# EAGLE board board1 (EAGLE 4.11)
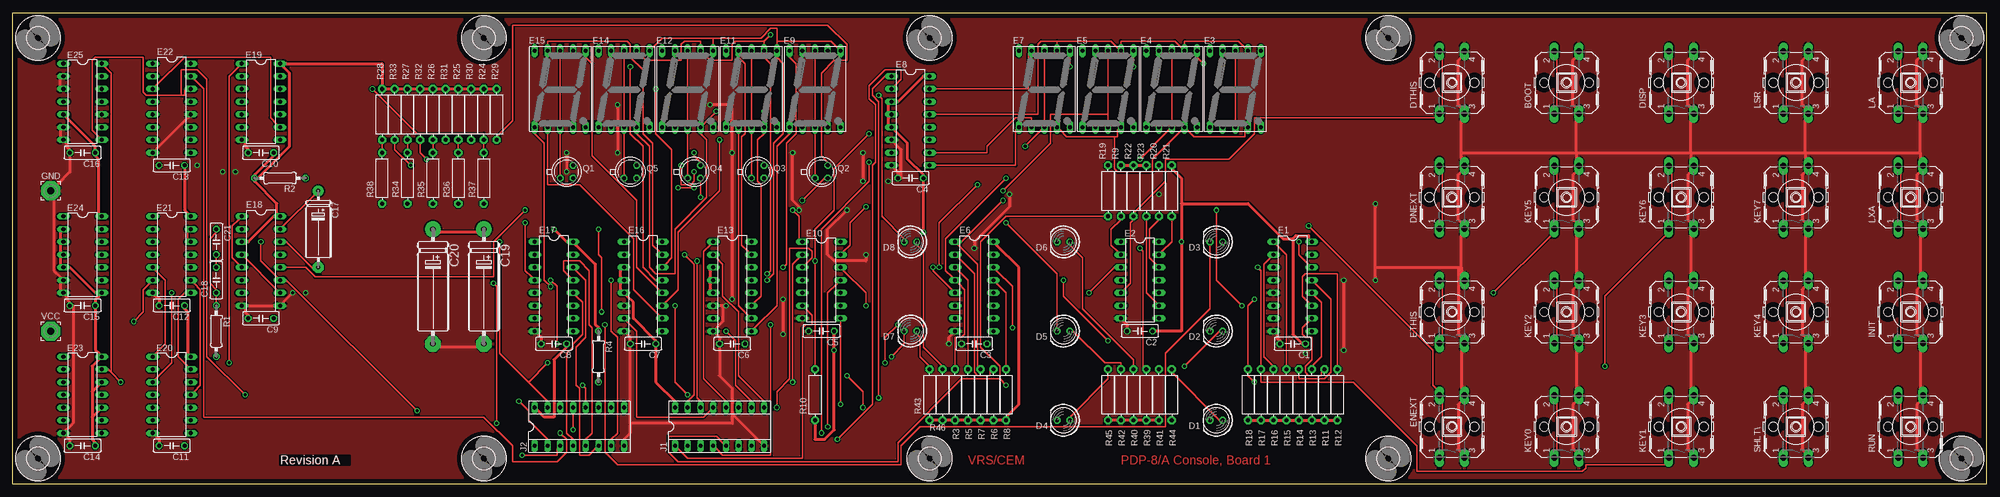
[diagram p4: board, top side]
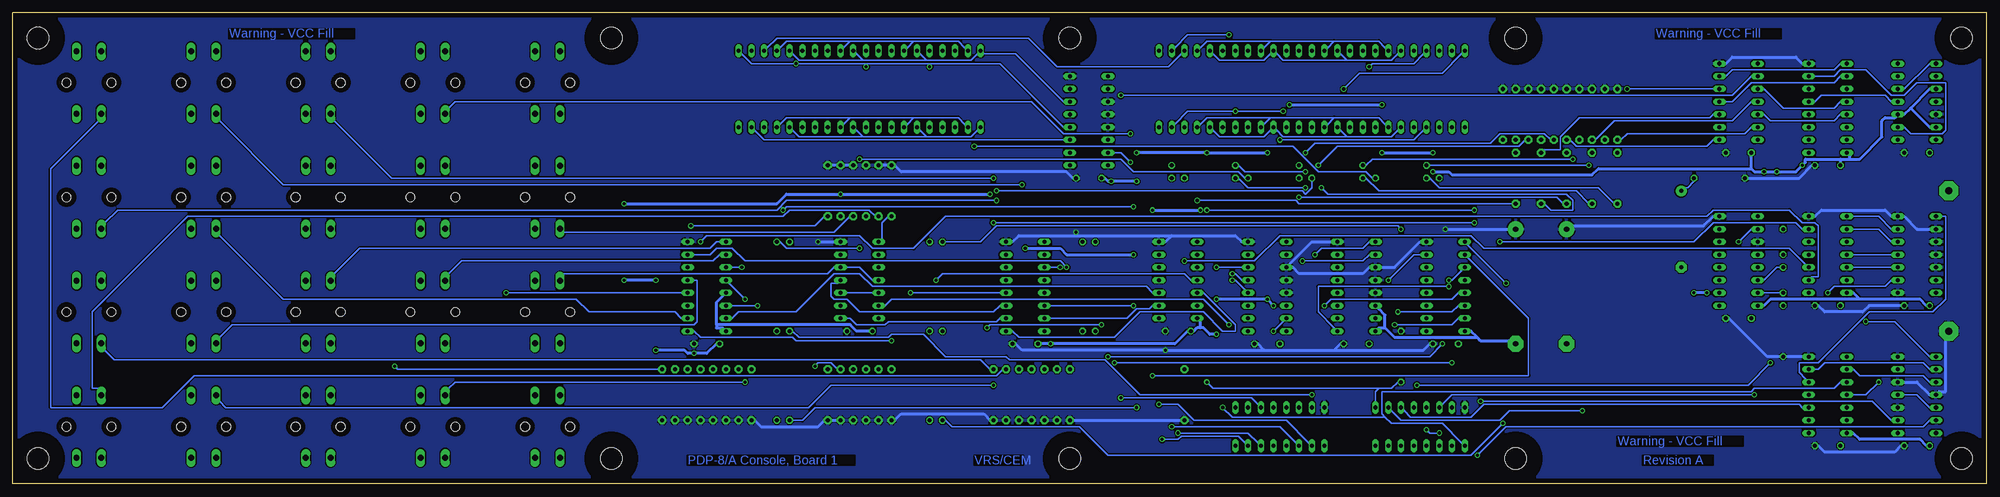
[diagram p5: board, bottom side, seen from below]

Size 393.7 x 93.98 mm. Coordinates in mm from the lower left corner, seen from the top.
Outline: 0,0 0,93.98 393.7,93.98 393.7,0 0,0
Copper layers (1*16): Top 0.035mm / dielectric 1.5mm / Bottom 0.035mm
Design rules "olimex10mil": minimum track width 10mil, minimum drill 24mil, track to track 10mil, track to pad 10mil, pad to pad 10mil, via to via 10mil, smd to smd 10mil, copper to edge 40mil, drill to drill 10mil, minimum pad ring 10mil, minimum via ring 8mil, stop-mask expansion 0mil, vias tented up to drill 0mil, thermal gap 10mil
Net classes: 1 Supply: width 0.635 mm

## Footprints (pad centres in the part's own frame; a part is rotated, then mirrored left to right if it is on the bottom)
B3F-40XX = drill 1.194 long: 1 -6.248,2.489; 2 6.248,2.489; 3 -6.248,-2.489; 4 6.248,-2.489 | hole 1.803: 0,-4.496; 0,4.496
C050-025X075 = drill 0.813 octagon: 1 -2.54,0; 2 2.54,0
E15-5 = drill 0.813 pad 2.159 round: + -7.62,0 | drill 0.813 pad 2.159 octagon: - 7.62,0
E22-6 = drill 1.016 pad 3.15 round: + -11.43,0 | drill 1.016 pad 3.15 octagon: - 11.43,0
LED5MM = drill 0.813 octagon: A -1.27,0; K 1.27,0
DIL16 = drill 0.813 long: 1 -8.89,-3.81; 2 -6.35,-3.81; 3 -3.81,-3.81; 4 -1.27,-3.81; 5 1.27,-3.81; 6 3.81,-3.81; 7 6.35,-3.81; 8 8.89,-3.81; 9 8.89,3.81; 10 6.35,3.81; 11 3.81,3.81; 12 1.27,3.81; 13 -1.27,3.81; 14 -3.81,3.81; 15 -6.35,3.81; 16 -8.89,3.81
DIL14 = drill 0.813 long: 1 -7.62,-3.81; 2 -5.08,-3.81; 3 -2.54,-3.81; 4 0,-3.81; 5 2.54,-3.81; 6 5.08,-3.81; 7 7.62,-3.81; 8 7.62,3.81; 9 5.08,3.81; 10 2.54,3.81; 11 0,3.81; 12 -2.54,3.81; 13 -5.08,3.81; 14 -7.62,3.81
HDSP-M = drill 0.813 long: 1 -5.08,-7.62; 2 -2.54,-7.62; 3 0,-7.62; 4 2.54,-7.62; 5 5.08,-7.62; 6 5.08,7.62; 7 2.54,7.62; 8 0,7.62; 9 -2.54,7.62; 10 -5.08,7.62
3,81/1,4 = drill 1.397 pad 3.81 octagon: 1 0,0
SOCKED-16 = drill 0.813 long: 1 -8.89,-3.81; 2 -6.35,-3.81; 3 -3.81,-3.81; 4 -1.27,-3.81; 5 1.27,-3.81; 6 3.81,-3.81; 7 6.35,-3.81; 8 8.89,-3.81; 9 8.89,3.81; 10 6.35,3.81; 11 3.81,3.81; 12 1.27,3.81; 13 -1.27,3.81; 14 -3.81,3.81; 15 -6.35,3.81; 16 -8.89,3.81
TO18 = drill 0.813 octagon: 1 -1.27,-1.27; 2 1.27,-1.27; 3 1.27,1.27
0207/10 = drill 0.813 octagon: 1 -5.08,0; 2 5.08,0
R-10 = drill 0.813 pad 1.6 octagon: 1 -5.08,0; 2 5.08,0
4,3 = hole 4.3: 0,0

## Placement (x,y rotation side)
BOOT  [B3F-40XX]  309.88,80.01 90 top
C1  0.01  [C050-025X075]  255.27,27.94 180 top
C2  0.01  [C050-025X075]  224.79,30.48 180 top
C3  0.01  [C050-025X075]  191.77,27.94 180 top
C4  0.01  [C050-025X075]  179.07,60.96 180 top
C5  0.01  [C050-025X075]  161.29,30.48 180 top
C6  0.01  [C050-025X075]  143.51,27.94 180 top
C7  0.01  [C050-025X075]  125.73,27.94 180 top
C8  0.01  [C050-025X075]  107.95,27.94 180 top
C9  0.01  [C050-025X075]  49.53,33.02 180 top
C10  0.01  [C050-025X075]  49.53,66.04 180 top
C11  0.01  [C050-025X075]  31.75,7.62 180 top
C12  0.01  [C050-025X075]  31.75,35.56 180 top
C13  0.01  [C050-025X075]  31.75,63.5 180 top
C14  0.01  [C050-025X075]  13.97,7.62 180 top
C15  0.01  [C050-025X075]  13.97,35.56 180 top
C16  0.01  [C050-025X075]  13.97,66.04 180 top
C17  1.0uf  [E15-5]  60.96,50.8 270 top
C18  47pf  [C050-025X075]  40.64,40.64 90 top
C19  220uf  [E22-6]  93.98,39.37 270 top
C20  6.8uf  [E22-6]  83.82,39.37 270 top
C21  33pf  [C050-025X075]  40.64,48.26 270 top
D1  MQ  [LED5MM]  240.03,12.7 180 top
D2  SR  [LED5MM]  240.03,30.48 180 top
D3  MD  [LED5MM]  240.03,48.26 180 top
D4  AC  [LED5MM]  209.55,12.7 180 top
D5  STATUS  [LED5MM]  209.55,30.48 180 top
D6  STATE  [LED5MM]  209.55,48.26 180 top
D7  BUS  [LED5MM]  179.07,30.48 180 top
D8  RUN  [LED5MM]  179.07,48.26 180 top
DISP  [B3F-40XX]  332.74,80.01 90 top
DNEXT  [B3F-40XX]  287.02,57.15 90 top
DTHIS  [B3F-40XX]  287.02,80.01 90 top
E1  74LS148N  [DIL16]  255.27,39.37 270 top
E2  74LS08N  [DIL14]  224.79,40.64 270 top
E3  HD-H101  [HDSP-M]  243.84,78.74 0 top
E4  HD-H101  [HDSP-M]  231.14,78.74 0 top
E5  HD-H101  [HDSP-M]  218.44,78.74 0 top
E6  74LS148N  [DIL16]  191.77,39.37 270 top
E7  HD-H101  [HDSP-M]  205.74,78.74 0 top
E8  7446N  [DIL16]  179.07,72.39 270 top
E9  HD-H101  [HDSP-M]  160.02,78.74 0 top
E10  74LS08N  [DIL14]  161.29,40.64 270 top
E11  HD-H101  [HDSP-M]  147.32,78.74 0 top
E12  HD-H101  [HDSP-M]  134.62,78.74 0 top
E13  7446N  [DIL16]  143.51,39.37 270 top
E14  HD-H101  [HDSP-M]  121.92,78.74 0 top
E15  HD-H101  [HDSP-M]  109.22,78.74 0 top
E16  7446N  [DIL16]  125.73,39.37 270 top
E17  74LS145N  [DIL16]  107.95,39.37 270 top
E18  74LS123N  [DIL16]  49.53,44.45 270 top
E19  7416N  [DIL14]  49.53,76.2 270 top
E20  74LS04N  [DIL14]  31.75,17.78 270 top
E21  74LS20N  [DIL14]  31.75,45.72 270 top
E22  74LS42N  [DIL16]  31.75,74.93 270 top
E23  74LS74N  [DIL14]  13.97,17.78 270 top
E24  74LS95N  [DIL14]  13.97,45.72 270 top
E25  74LS90N  [DIL14]  13.97,76.2 270 top
ENEXT  [B3F-40XX]  287.02,11.43 90 top
ETHIS  [B3F-40XX]  287.02,34.29 90 top
GND  [3,81/1,4]  7.62,58.42 0 top
INIT  [B3F-40XX]  378.46,34.29 90 top
J1  [SOCKED-16]  140.97,11.43 0 top
J2  [SOCKED-16]  113.03,11.43 0 top
KEY0  [B3F-40XX]  309.88,11.43 90 top
KEY1  [B3F-40XX]  332.74,11.43 90 top
KEY2  [B3F-40XX]  309.88,34.29 90 top
KEY3  [B3F-40XX]  332.74,34.29 90 top
KEY4  [B3F-40XX]  355.6,34.29 90 top
KEY5  [B3F-40XX]  309.88,57.15 90 top
KEY6  [B3F-40XX]  332.74,57.15 90 top
KEY7  [B3F-40XX]  355.6,57.15 90 top
LA  [B3F-40XX]  378.46,80.01 90 top
LSR  [B3F-40XX]  355.6,80.01 90 top
LXA  [B3F-40XX]  378.46,57.15 90 top
Q1  MPSA05  [TO18]  110.49,62.23 0 top
Q2  MPSA05  [TO18]  161.29,62.23 0 top
Q3  MPSA05  [TO18]  148.59,62.23 0 top
Q4  MPSA05  [TO18]  135.89,62.23 0 top
Q5  MPSA05  [TO18]  123.19,62.23 0 top
R1  10K  [0207/10]  40.64,30.48 270 top
R2  6.8K  [0207/10]  53.34,60.96 0 top
R3  1K  [R-10]  187.96,17.78 90 top
R4  10K  [0207/10]  116.84,25.4 270 top
R5  1K  [R-10]  190.5,17.78 90 top
R6  1K  [R-10]  195.58,17.78 90 top
R7  1K  [R-10]  193.04,17.78 90 top
R8  1K  [R-10]  198.12,17.78 90 top
R9  1K  [R-10]  220.98,58.42 270 top
R10  1K  [R-10]  160.02,17.78 90 top
R11  1K  [R-10]  261.62,17.78 90 top
R12  1K  [R-10]  264.16,17.78 90 top
R13  1K  [R-10]  259.08,17.78 90 top
R14  1K  [R-10]  256.54,17.78 90 top
R15  1K  [R-10]  254,17.78 90 top
R16  1K  [R-10]  251.46,17.78 90 top
R17  1K  [R-10]  248.92,17.78 90 top
R18  1K  [R-10]  246.38,17.78 90 top
R19  1K  [R-10]  218.44,58.42 270 top
R20  1K  [R-10]  228.6,58.42 270 top
R21  1K  [R-10]  231.14,58.42 270 top
R22  1K  [R-10]  223.52,58.42 270 top
R23  1K  [R-10]  226.06,58.42 270 top
R24  470  [R-10]  93.98,73.66 270 top
R25  470  [R-10]  88.9,73.66 270 top
R26  470  [R-10]  83.82,73.66 270 top
R27  470  [R-10]  78.74,73.66 270 top
R28  470  [R-10]  73.66,73.66 270 top
R29  10  [R-10]  96.52,73.66 270 top
R30  10  [R-10]  91.44,73.66 270 top
R31  10  [R-10]  86.36,73.66 270 top
R32  10  [R-10]  81.28,73.66 270 top
R33  27  [R-10]  76.2,73.66 270 top
R34  27  [R-10]  78.74,60.96 90 top
R35  27  [R-10]  83.82,60.96 90 top
R36  27  [R-10]  88.9,60.96 90 top
R37  27  [R-10]  93.98,60.96 90 top
R38  27  [R-10]  73.66,60.96 90 top
R39  330  [R-10]  226.06,17.78 90 top
R40  330  [R-10]  223.52,17.78 90 top
R41  330  [R-10]  228.6,17.78 90 top
R42  330  [R-10]  220.98,17.78 90 top
R43  330  [R-10]  182.88,17.78 90 top
R44  330  [R-10]  231.14,17.78 90 top
R45  330  [R-10]  218.44,17.78 90 top
R46  330  [R-10]  185.42,17.78 90 top
RUN  [B3F-40XX]  378.46,11.43 90 top
SHLT\  [B3F-40XX]  355.6,11.43 90 top
U$2  [4,3]  5.08,5.08 0 top
U$11  [4,3]  93.98,5.08 0 top
U$12  [4,3]  5.08,88.9 0 top
U$13  [4,3]  182.88,5.08 0 top
U$14  [4,3]  274.32,5.08 0 top
U$15  [4,3]  388.62,5.08 0 top
U$16  [4,3]  388.62,88.9 0 top
U$17  [4,3]  274.32,88.9 0 top
U$18  [4,3]  182.88,88.9 0 top
U$19  [4,3]  93.98,88.9 0 top
VCC  [3,81/1,4]  7.62,30.48 0 top

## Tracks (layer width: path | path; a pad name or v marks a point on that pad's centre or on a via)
AA  (via drill 0.61)
  Top 0.254: E14.7 125.09,85.72 126.36,84.45 133.35,84.45 133.35,87.63 133.99,88.27 137.16,88.27 137.16,87.63 E12.7 137.79,85.72 139.06,84.45 143.51,84.45 143.51,87.63 144.15,88.27 149.86,88.27 | v150.5,41.91 151.13,42.55 151.13,83.82 149.86,85.09 E11.7 149.86,87.63 149.86,88.27 | 149.86,88.27 v151.13,89.53
  Bottom 0.254: v150.5,41.91 149.86,41.91 148.59,40.64 E13.13 | v151.13,89.53 159.38,89.53 161.93,87 E9.7
AB  (via drill 0.61)
  Top 0.254: 139.7,88.9 129.54,88.9 127.64,87 E14.6 | 139.7,88.9 139.7,87.63 E12.6 | v150.5,40.64 151.76,41.91 151.76,67.94 153.67,69.85 153.67,83.82 152.4,85.09 E11.6 152.4,87.63 152.4,88.27 | 152.4,88.27 163.19,88.27 164.47,87 E9.6 | 139.7,88.9 149.22,88.9 151.13,90.81 152.4,90.81 152.4,88.27
  Bottom 0.254: v150.5,40.64 149.86,40.64 147.96,38.73 E13.12
AC  (via drill 0.61)
  Top 0.254: E14.4 124.46,69.85 127,67.31 127,43.18 128.27,41.91 132.08,41.91 132.08,50.8 138.43,57.15 138.43,68.58 137.16,69.85 E12.4 137.79,71.75 v140.34,74.3 | E13.11 147.96,36.2 149.22,37.47 149.22,59.69 148.59,60.33 148.59,68.58 149.86,69.85 E11.4 149.86,72.39 v149.86,74.3
  Bottom 0.254: E9.4 161.93,71.75 159.38,74.3 v149.86,74.3 v140.34,74.3
AD
  Top 0.254: E13.10 146.69,33.66 144.78,35.56 144.78,69.85 E11.2
  Bottom 0.254: 130.18,73.03 121.28,73.03 120.02,71.75 E14.2 | 130.18,73.03 131.44,71.75 E12.2 | 142.88,73.03 144.15,71.75 E11.2 | 142.88,73.03 130.18,73.03 | 142.88,73.03 155.57,73.03 156.84,71.75 E9.2
ADDR0
  Top 0.254: J1.9 149.86,16.51 144.78,21.59 144.78,34.29 141.6,37.47 141.6,43.81 140.34,45.09 E13.2
ADDR1
  Top 0.254: J1.12 142.24,16.51 137.79,20.95 137.79,46.35 139.06,47.62 E13.1
ADDR2  (via drill 0.61)
  Top 0.254: v142.24,30.48 144.15,28.57 144.15,19.68 147.32,16.51 J1.10
  Bottom 0.254: v142.24,30.48 140.34,32.38 E13.7
AE
  Top 0.254: E13.9 147.96,31.11 152.4,35.56 152.4,67.31 154.94,69.85 E9.1
  Bottom 0.254: 127.64,69.22 118.75,69.22 117.47,70.48 E14.1 | 127.64,69.22 128.91,70.48 E12.1 | 127.64,69.22 140.34,69.22 141.6,70.48 E11.1 142.88,70.48 144.15,69.22 153.03,69.22 154.31,70.48 E9.1
AF
  Top 0.254: E13.15 146.69,46.35 145.41,47.62 145.41,69.22 146.05,69.85 146.05,83.82 144.78,85.09 E11.9
  Bottom 0.254: 130.18,88.27 121.28,88.27 120.02,87 E14.9 | 130.18,88.27 131.44,87 E12.9 | 142.88,88.27 144.15,87 E11.9 | 142.88,88.27 130.18,88.27 | 142.88,88.27 155.57,88.27 156.84,87 E9.9
AG  (via drill 0.61)
  Top 0.254: v153.67,43.18 154.31,43.81 154.31,67.94 156.21,69.85 156.21,83.82 154.94,85.09 E9.10
  Bottom 0.254: 127.64,84.45 118.75,84.45 117.47,85.72 E14.10 | 127.64,84.45 128.91,85.72 E12.10 | 127.64,84.45 140.34,84.45 141.6,85.72 E11.10 142.88,85.72 144.15,84.45 153.03,84.45 154.31,85.72 E9.10 | v153.67,43.18 148.59,43.18 E13.14
BEMA0  (via drill 0.61)
  Top 0.254: v136.53,44.45 136.53,17.14 137.16,16.51 J1.14
  Bottom 0.254: v136.53,44.45 124.46,44.45 123.19,45.72 E16.2
BEMA1  (via drill 0.61)
  Top 0.254: v133.99,45.72 135.89,43.81 135.89,17.78 134.62,16.51 J1.15
  Bottom 0.254: v133.99,45.72 132.72,46.99 124.46,46.99 123.19,48.26 E16.1
BEMA2
  Top 0.254: J1.13 139.06,14.61 137.79,13.34 124.46,13.34 124.46,30.48 122.56,32.38 E16.7
BOOT  (via drill 0.61)
  Top 0.254: BOOT.1 307.98,74.93 307.98,85.09 BOOT.2 | R10.2 160.02,23.5 v160.02,44.45 160.02,50.8 163.83,54.61 163.83,62.87 v170.81,69.85
  Bottom 0.254: v160.02,44.45 146.05,44.45 140.97,49.53 102.87,49.53 100.33,46.99 39.37,46.99 36.2,43.81 E21.10 | v170.81,69.85 184.15,69.85 190.5,76.2 305.44,76.2 306.7,74.93 BOOT.1
BPWR-OK  (via drill 0.61)
  Top 0.254: v49.53,48.26 49.53,44.45 52.7,41.27 E18.11 54.61,40.64 v80.64,14.61
  Bottom 0.254: v49.53,48.26 46.99,50.8 E18.2 | v80.64,14.61 95.25,14.61 97.16,12.7 116.84,12.7 118.75,14.61 J2.10
BRUN  (via drill 0.61)
  Top 0.254: v43.18,24.13 43.18,81.28 45.09,83.19 E19.1 | v113.67,19.68 114.3,19.05 114.3,16.51 J2.12
  Bottom 0.254: v43.18,24.13 47.62,19.68 v113.67,19.68
DA
  Top 0.254: 208.28,88.27 205.1,88.27 204.47,87.63 204.47,73.66 184.15,73.66 E8.13 | 208.28,88.27 208.28,87.63 E7.7 | 208.28,88.27 219.07,88.27 220.34,87 E5.7 220.98,87.63 220.98,88.27 231.78,88.27 233.04,87 E4.7 233.68,87.63 233.68,88.27 244.47,88.27 245.75,87 E3.7
DB  (via drill 0.61)
  Top 0.254: v210.82,83.19 210.82,85.09 E7.6 | v223.52,83.19 223.52,85.09 E5.6 | v237.49,83.82 236.22,85.09 E4.6
  Bottom 0.254: 223.52,83.82 v237.49,83.82 246.38,83.82 248.28,85.72 E3.6 | 210.82,83.82 223.52,83.82 | 210.82,83.82 196.85,83.82 184.15,71.12 E8.12 | 210.82,83.82 v210.82,83.19 | 223.52,83.82 v223.52,83.19
DC
  Top 0.254: 219.71,69.22 220.34,69.22 220.34,70.48 E5.4 | 219.71,69.22 210.19,69.22 208.91,70.48 E7.4 | E3.4 245.75,70.48 245.75,69.22 235.59,69.22 234.31,70.48 E4.4 233.04,70.48 227.33,64.77 227.33,62.23 220.34,62.23 219.71,62.87 219.71,69.22
  Bottom 0.254: E8.11 184.15,68.58 243.84,68.58 245.75,70.48 E3.4
DD
  Top 0.254: E8.10 184.15,66.04 194.31,66.04 194.31,67.31 200.03,73.03 203.2,73.03 203.2,72.39 E7.2
  Bottom 0.254: 214,73.03 215.26,71.75 E5.2 | 214,73.03 205.1,73.03 203.84,71.75 E7.2 | 226.69,73.03 227.97,71.75 E4.2 | 214,73.03 226.69,73.03 | 226.69,73.03 239.4,73.03 240.66,71.75 E3.2
DE
  Top 0.254: E8.9 184.15,63.5 200.03,63.5 200.03,70.48 E7.1
  Bottom 0.254: 211.46,69.22 212.72,70.48 E5.1 | 211.46,69.22 202.56,69.22 201.29,70.48 E7.1 | 224.16,69.22 225.43,70.48 E4.1 | 211.46,69.22 224.16,69.22 | 224.16,69.22 236.85,69.22 238.12,70.48 E3.1
DF
  Top 0.254: E8.15 184.15,78.74 202.56,78.74 202.56,85.72 E7.9
  Bottom 0.254: 214,88.27 215.26,87 E5.9 | 214,88.27 205.1,88.27 203.84,87 E7.9 | 226.69,88.27 227.97,87 E4.9 | 214,88.27 226.69,88.27 | 226.69,88.27 239.4,88.27 240.66,87 E3.9
DG
  Bottom 0.254: E8.14 184.15,76.2 193.68,85.72 200.03,85.72 E7.10 201.29,85.72 202.56,84.45 211.46,84.45 | 211.46,84.45 212.72,85.72 E5.10 | 224.16,84.45 225.43,85.72 E4.10 | 211.46,84.45 224.16,84.45 | 224.16,84.45 236.85,84.45 238.12,85.72 E3.10
DISP  (via drill 0.61)
  Top 0.254: DISP.1 330.83,74.93 330.83,85.09 DISP.2 | R3.2 187.96,23.5 187.96,29.21 189.23,29.21 189.87,29.84 189.87,38.73 188.59,40.01 E6.4 187.32,41.27 186.06,42.55 186.06,48.9 v198.12,60.96
  Bottom 0.254: v198.12,60.96 318.13,60.96 329.56,72.39 DISP.1
DISP0
  Top 0.254: J2.5 114.3,8.89 115.57,10.16 115.57,31.11 114.94,31.75 114.94,42.55 113.03,44.45 109.86,44.45 109.86,42.55 111.12,41.27 E17.13
DISP1
  Top 0.254: J2.6 116.2,6.99 114.94,5.71 113.03,5.71 113.03,19.05 112.39,19.68 112.39,27.3 114.3,29.21 114.3,40.64 112.39,42.55 E17.14
DISP2  (via drill 0.61)
  Top 0.254: v119.38,40.64 119.38,30.48 120.65,29.21 120.65,10.16 119.38,8.89 J2.7
  Bottom 0.254: v119.38,40.64 114.3,45.72 113.03,45.72 E17.15
DISPINH
  Top 0.254: J2.4 111.76,8.89 110.49,10.16 110.49,26.04 111.76,27.3 111.76,27.94 113.67,29.84 113.67,36.2 112.39,37.47 E17.12
DISPLAY0  (via drill 0.61)
  Top 0.254: v164.47,8.89 171.45,15.88 171.45,63.5 172.09,64.14 172.09,75.56 170.81,76.83 170.81,79.38 173.99,82.55 177.16,82.55 177.16,80.64 175.9,79.38 E8.2
  Bottom 0.254: v164.47,8.89 161.29,8.89 160.66,9.53 149.22,9.53 147.96,8.26 J1.7
DISPLAY1  (via drill 0.61)
  Top 0.254: v172.72,17.14 172.72,76.2 171.45,77.47 171.45,78.74 173.99,81.28 E8.1
  Bottom 0.254: v172.72,17.14 146.69,17.14 145.41,15.88 J1.11
DISPLAY2  (via drill 0.61)
  Top 0.254: v161.29,10.16 161.29,50.8 170.81,60.33 v170.81,64.14
  Bottom 0.254: v161.29,10.16 147.32,10.16 145.41,8.26 J1.6 | v170.81,64.14 172.72,66.04 173.99,66.04 E8.7
DNEXT
  Top 0.254: DNEXT.1 285.12,52.07 285.12,62.23 DNEXT.2 | E2.9 227.97,36.2 226.06,38.1 226.06,52.7 R23.2
  Bottom 0.254: DNEXT.1 283.85,50.16 229.87,50.16 226.69,53.34 R23.2
DTHIS
  Top 0.254: DTHIS.2 285.12,85.09 285.12,74.93 DTHIS.1 283.85,73.03 247.65,73.03 247.65,69.85 242.57,64.77 229.87,64.77 229.87,60.33 223.52,53.98 R22.2 223.52,52.7 222.88,52.07 222.88,40.01 221.62,38.73 E2.5
  Bottom 0.254: E2.5 222.25,38.1 227.33,38.1 E2.10
ENEXT  (via drill 0.61)
  Top 0.254: E2.13 229.24,46.35 231.14,48.26 231.14,52.7 R21.2 | ENEXT.1 285.12,6.35 285.12,16.51 ENEXT.2 283.85,19.05 283.21,19.68 283.21,26.67 v258.44,51.44
  Bottom 0.254: v258.44,51.44 233.68,51.44 231.78,53.34 R21.2
ETHIS
  Top 0.254: ETHIS.1 285.12,29.21 285.12,39.37 ETHIS.2 | R20.2 228.6,52.7 226.69,50.8 226.69,45.09 227.97,43.81 E2.12
  Bottom 0.254: E2.4 222.25,40.64 224.79,43.18 227.33,43.18 E2.12 229.87,43.18 231.14,41.91 283.85,41.91 ETHIS.2
EXTPUL\  (via drill 0.61)
  Top 0.254: v155.57,20.32 155.57,43.81 156.84,45.09 E10.2
  Bottom 0.254: 121.28,19.05 118.75,19.05 117.47,20.32 R4.2 | 121.28,19.05 121.92,18.41 121.92,16.51 J2.9 | v155.57,20.32 154.31,19.05 121.28,19.05
FUN\  (via drill 0.61)
  Top 0.254: E21.12 34.92,48.9 34.92,50.16 E21.13 | 102.87,20.32 97.16,26.04 v97.16,48.26 | 102.87,20.32 106.68,16.51 J2.15 | v199.39,31.11 199.39,39.37 196.22,42.55 E6.14 | v176.53,31.75 173.99,29.21 v173.99,24.13 | 102.87,20.32 v106.68,24.13
  Bottom 0.254: v97.16,48.26 58.42,48.26 54.61,52.07 38.1,52.07 36.83,50.8 E21.13 | v199.39,31.11 198.75,31.75 v176.53,31.75 | v106.68,24.13 v173.99,24.13
GND  (via drill 0.61)
  Top 0.635: v110.49,66.04 v110.49,62.23 | v120.65,75.56 v120.65,66.04 | v139.06,75.56 143.51,75.56 v143.51,66.04 v143.51,36.83 | v169.54,66.04 v169.54,60.33 | v153.67,36.83 v153.67,29.84 | v155.57,66.04 155.57,56.52 156.84,55.24 v156.84,54.61 | v166.37,54.61 162.56,50.8 162.56,45.72 163.83,44.45 170.18,44.45 v170.18,45.72 | v191.77,46.99 191.77,48.26 198.75,55.24 v198.75,57.78 | 271.78,43.18 v271.78,55.88 | v271.78,40.64 271.78,43.18 | v265.43,26.67 v265.43,40.64 | 380.37,66.04 380.37,72.39 LA.3 380.37,74.93 379.73,75.56 379.73,84.45 380.37,85.09 LA.4 | 380.37,66.04 380.37,64.77 LXA.4 380.37,62.23 379.73,61.59 379.73,52.7 380.37,52.07 LXA.3 380.37,49.53 380.37,41.91 INIT.4 380.37,39.37 379.73,38.73 379.73,29.84 380.37,29.21 INIT.3 380.37,26.67 380.37,19.05 RUN.4 380.37,16.51 379.73,15.88 379.73,6.99 380.37,6.35 RUN.3 | 357.5,66.04 357.5,72.39 LSR.3 357.5,74.93 356.87,75.56 356.87,84.45 357.5,85.09 LSR.4 | 357.5,66.04 357.5,64.77 KEY7.4 357.5,62.23 356.87,61.59 356.87,52.7 357.5,52.07 KEY7.3 357.5,49.53 357.5,41.91 KEY4.4 357.5,39.37 356.87,38.73 356.87,29.84 357.5,29.21 KEY4.3 357.5,26.67 357.5,19.05 SHLT\.4 357.5,16.51 356.87,15.88 356.87,6.99 357.5,6.35 SHLT\.3 | 334.64,66.04 334.64,72.39 DISP.3 334.64,74.93 334.01,75.56 334.01,84.45 334.64,85.09 DISP.4 | 334.64,66.04 334.64,64.77 KEY6.4 334.64,62.23 334.01,61.59 334.01,52.7 334.64,52.07 KEY6.3 334.64,49.53 334.64,41.91 KEY3.4 334.64,39.37 334.01,38.73 334.01,29.84 334.64,29.21 KEY3.3 334.64,26.67 334.64,19.05 KEY1.4 334.64,16.51 334.01,15.88 334.01,6.99 334.64,6.35 KEY1.3 | 311.79,66.04 311.79,72.39 BOOT.3 311.79,74.93 311.15,75.56 311.15,84.45 311.79,85.09 BOOT.4
  Top 0.635: 311.79,66.04 311.79,64.77 KEY5.4 311.79,62.23 311.15,61.59 311.15,52.7 311.79,52.07 KEY5.3 311.79,49.53 311.79,41.91 KEY2.4 311.79,39.37 311.15,38.73 311.15,29.84 311.79,29.21 KEY2.3 311.79,26.67 311.79,19.05 KEY0.4 311.79,16.51 311.15,15.88 311.15,6.99 311.79,6.35 KEY0.3 | C14.2 11.43,8.26 11.43,8.89 10.79,9.53 E23.7 10.79,10.79 12.06,12.06 12.06,35.56 C15.2 11.43,36.2 10.79,36.83 10.79,37.47 E24.7 9.53,38.73 9.53,40.01 E24.6 9.53,41.27 8.26,42.55 8.26,57.15 GND.1 8.89,59.69 11.43,62.23 11.43,65.41 C16.2 11.43,66.67 10.79,67.31 10.79,67.94 E25.7 9.53,69.22 9.53,70.48 E25.6 | E20.7 28.57,9.53 29.21,8.89 29.21,8.26 C11.2 | v55.88,38.1 53.98,36.2 E18.9 52.07,35.56 46.99,35.56 E18.8 46.35,34.92 46.35,34.29 46.99,33.66 C9.2 | E21.7 28.57,37.47 29.21,36.83 29.21,36.2 C12.2 | 123.19,12.06 123.19,27.3 C7.2 123.19,28.57 123.19,29.21 122.56,29.84 E16.8 | 123.19,12.06 123.19,10.16 121.92,8.89 J2.8 | E17.8 104.78,29.84 105.41,29.21 105.41,28.57 C8.2 | C20.- 85.09,27.3 92.71,27.3 C19.- | E2.7 221.62,32.38 222.25,31.75 222.25,31.11 C2.2 | C1.2 252.73,28.57 252.09,29.21 252.09,29.84 E1.8 | 143.51,13.97 149.22,8.26 J1.8 | 143.51,13.97 143.51,19.05 140.97,21.59 140.97,27.3 C6.2 140.97,28.57 140.97,29.21 140.34,29.84 E13.8 140.34,31.11 141.6,32.38 141.6,35.56 | 288.93,66.04 288.93,72.39 DTHIS.3 288.93,74.93 288.29,75.56 288.29,84.45 288.93,85.09 DTHIS.4 | 288.93,66.04 288.93,64.77 DNEXT.4 288.93,62.23 288.29,61.59 288.29,52.7 288.93,52.07 DNEXT.3 288.93,49.53 288.93,43.18 | ENEXT.3 288.93,6.35 288.29,6.99 288.29,15.88 288.93,16.51 ENEXT.4 288.93,19.05 288.93,26.67 ETHIS.3 288.93,29.21 288.29,29.84 288.29,43.18
  Top 0.635: 288.93,43.18 288.93,41.91 ETHIS.4 | C10.2 46.99,66.67 46.35,67.31 46.35,67.94 E19.7 | E25.3 9.53,79.38 9.53,80.64 E25.2 | E22.12 34.92,73.03 28.57,66.67 E22.8 | v142.24,35.56 141.6,35.56 | 141.6,35.56 140.97,35.56 E13.6 | E8.8 175.9,62.87 176.53,62.23 176.53,61.59 C4.2 177.16,60.96 177.16,66.67 175.9,67.94 E8.6 | v186.69,27.94 186.69,29.21 187.32,29.84 E6.8 | 271.78,43.18 288.29,43.18 | 288.29,43.18 288.93,43.18 | 123.19,12.06 143.51,12.06 143.51,13.97 | 288.93,66.04 311.79,66.04 | 311.79,66.04 334.64,66.04 | 334.64,66.04 357.5,66.04 | 357.5,66.04 380.37,66.04
  Bottom 0.635: v55.88,38.1 v58.42,38.1 | 29.21,64.77 36.2,64.77 36.2,64.14 v36.83,63.5 38.1,62.23 v41.91,62.23 v44.45,62.23 46.35,62.23 46.99,62.87 | 29.21,64.77 27.3,64.77 | 27.3,64.77 25.4,64.77 20.95,69.22 20.95,72.39 20.32,73.03 18.41,73.03 E25.10 16.51,73.66 15.24,74.93 | 46.99,62.87 77.47,62.87 78.74,61.59 106.68,61.59 107.31,62.23 v110.49,62.23 | v120.65,66.04 v110.49,66.04 | v139.06,75.56 v120.65,75.56 | v142.24,35.56 v143.51,36.83 v153.67,36.83 | v169.54,66.04 v155.57,66.04 v143.51,66.04 | v169.54,60.33 v174.62,60.33 175.26,60.33 175.9,60.96 C4.2 | v153.67,29.84 154.94,29.84 156.21,31.11 156.84,31.11 | 156.84,31.11 156.84,32.38 E10.7 | v166.37,54.61 v156.84,54.61 | v170.18,45.72 183.51,45.72 184.78,46.99 v191.77,46.99 | v198.75,57.78 v228.6,57.78 239.4,57.78 241.3,55.88 v271.78,55.88 | v265.43,40.64 v271.78,40.64 | v265.43,26.67 259.71,26.67 259.08,26.04 v257.81,26.04 255.27,26.04 253.37,27.94 C1.2 | C14.2 12.06,7.62 13.34,8.89 25.4,8.89 26.67,10.16 E20.7 | 25.4,36.83 26.67,38.1 E21.7 | 25.4,36.83 13.34,36.83 12.06,35.56 C15.2 | 25.4,36.83 43.18,36.83 44.45,35.56 E18.8 | 120.02,31.11 120.02,33.66 121.28,34.92 E16.6 | 120.02,31.11 121.28,31.11 E16.8 | 101.6,29.21 100.97,28.57 95.25,28.57 C19.- | 101.6,29.21 102.87,30.48 E17.8 | 120.02,31.11 118.11,29.21 101.6,29.21 | 253.37,31.75 253.37,31.11 252.09,31.11 E1.8 | 253.37,31.75 253.37,36.2 252.09,37.47 E1.5 | 253.37,31.75 226.69,31.75 225.43,30.48 222.88,30.48 C2.2 | 27.3,64.77 27.3,65.41 E22.8 | 29.21,64.77 29.21,64.14 C13.2 | 156.84,31.11 157.48,31.11 158.12,30.48 C5.2 159.38,30.48 161.93,27.94 v186.69,27.94 188.59,27.94 C3.2
  Bottom 0.635: 15.24,74.93 11.43,78.74 E25.3 | 46.99,62.87 46.99,65.41 C10.2 | 15.24,74.93 11.43,71.12 E25.6
  pour Top (isolate 0.254): 0,0 0,93.98 393.7,93.98 393.7,0
INIT
  Top 0.254: INIT.1 376.56,29.21 376.56,39.37 INIT.2 | E6.13 196.22,40.01 198.12,38.1 198.12,23.5 R8.2
  Bottom 0.254: INIT.1 375.29,26.67 373.38,24.77 200.66,24.77 198.75,22.86 R8.2
KEY0  (via drill 0.61)
  Top 0.254: KEY0.1 307.98,6.35 307.98,16.51 KEY0.2 | v247.65,36.83 246.38,35.56 246.38,23.5 R18.2 246.38,22.23 246.38,21.59 v247.65,20.32
  Bottom 0.254: v247.65,36.83 250.82,40.01 E1.4 | v247.65,20.32 305.44,20.32 306.7,19.05 KEY0.2
KEY1  (via drill 0.61)
  Top 0.254: KEY1.2 330.83,16.51 330.83,6.35 KEY1.1 329.56,3.81 313.69,3.81 313.69,3.17 313.06,2.54 280.04,2.54 280.04,7.62 267.33,20.32 248.92,20.32 248.92,22.23 R17.2 248.92,23.5 248.92,42.55 v248.28,43.18
  Bottom 0.254: v248.28,43.18 250.19,43.18 E1.3
KEY2
  Top 0.254: KEY2.1 307.98,29.21 307.98,39.37 KEY2.2 | E1.2 250.82,45.09 249.56,43.81 249.56,25.4 251.46,23.5 R16.2
  Bottom 0.254: KEY2.2 306.7,41.91 304.17,44.45 254,44.45 252.73,45.72 E1.2
KEY3
  Top 0.254: KEY3.1 330.83,29.21 330.83,39.37 KEY3.2 | E1.1 252.09,47.62 254,45.72 254,23.5 R15.2
  Bottom 0.254: KEY3.2 329.56,41.91 324.49,46.99 254.63,46.99 253.37,48.26 252.73,48.26 E1.1
KEY4
  Top 0.254: KEY4.1 353.69,29.21 353.69,39.37 KEY4.2 | E1.13 259.71,40.01 262.89,36.83 262.89,22.23 261.62,20.95 256.54,20.95 256.54,22.23 R14.2
  Bottom 0.254: KEY4.1 352.43,29.21 349.88,31.75 257.81,31.75 257.18,32.38 257.18,40.64 257.81,40.64 E1.13
KEY5  (via drill 0.61)
  Top 0.254: KEY5.2 307.98,62.23 307.98,52.07 KEY5.1 306.7,49.53 v295.27,38.1 | E1.12 259.71,37.47 260.99,36.2 260.99,25.4 259.08,23.5 R13.2
  Bottom 0.254: v295.27,38.1 260.35,38.1 E1.12
KEY6  (via drill 0.61)
  Top 0.254: KEY6.2 330.83,62.23 330.83,52.07 KEY6.1 329.56,49.53 317.5,37.47 v317.5,23.5 | E1.11 258.44,36.2 257.18,37.47 257.18,41.27 257.81,41.91 264.16,41.91 264.16,23.5 R12.2
  Bottom 0.254: v317.5,23.5 316.87,22.86 264.8,22.86 R12.2
KEY7
  Top 0.254: E1.10 258.44,32.38 257.18,31.11 257.18,29.84 257.81,29.21 259.08,29.21 259.08,24.77 257.81,23.5 257.81,22.23 258.44,21.59 260.99,21.59 260.99,22.86 R11.2 | KEY7.1 353.69,52.07 353.69,62.23 KEY7.2
  Bottom 0.254: E1.10 260.35,33.02 261.62,34.29 278.76,34.29 281.31,36.83 339.73,36.83 352.43,49.53 KEY7.1
KEY-F\  (via drill 0.61)
  Top 0.254: v101.6,5.71 108.58,5.71 108.58,6.99 J2.3
  Bottom 0.254: v101.6,5.71 95.89,11.43 12.7,11.43 11.43,12.7 E23.6
KEYSTB  (via drill 0.61)
  Top 0.254: v100.97,16.51 102.87,14.61 102.87,12.7 106.68,8.89 J2.2
  Bottom 0.254: v100.97,16.51 22.86,16.51 19.05,12.7 E23.9
KFUN0\  (via drill 0.61)
  Top 0.254: v162.56,11.43 162.56,38.1 164.47,40.01 E10.11
  Bottom 0.254: v162.56,11.43 140.97,11.43 137.79,8.26 J1.3
KFUN1\  (via drill 0.61)
  Top 0.254: v165.1,15.88 165.1,32.38 E10.8
  Bottom 0.254: v165.1,15.88 161.29,15.88 158.12,12.7 139.7,12.7 135.25,8.26 J1.2
KFUN2\
  Top 0.254: J1.1 132.72,6.99 134.62,5.08 157.48,5.08 157.48,31.11 158.12,31.75 159.38,31.75 159.38,33.66 158.12,34.92 E10.6
LA
  Top 0.254: LA.1 376.56,74.93 376.56,85.09 LA.2 | E6.2 188.59,45.09 191.77,41.91 191.77,22.23 192.41,21.59 194.94,21.59 194.94,22.86 R6.2
  Bottom 0.254: LA.1 376.56,72.39 386.08,62.87 386.08,15.24 363.86,15.24 357.5,21.59 197.49,21.59 196.22,22.86 R6.2
LSR  (via drill 0.61)
  Top 0.254: LSR.1 353.69,74.93 353.69,85.09 LSR.2 | E6.3 188.59,42.55 190.5,40.64 190.5,23.5 R5.2 | v192.41,59.69 184.78,52.07 v184.78,43.18
  Bottom 0.254: v192.41,59.69 339.73,59.69 352.43,72.39 LSR.1 | v184.78,43.18 186.69,43.18 E6.3
LXA  (via drill 0.61)
  Top 0.254: LXA.1 376.56,52.07 376.56,62.23 LXA.2 | R7.2 192.41,22.86 192.41,43.81 188.59,47.62 E6.1 189.23,48.26 v197.49,56.52
  Bottom 0.254: v197.49,56.52 239.4,56.52 241.3,54.61 372.75,54.61 375.29,52.07 LXA.1
MCLOCK  (via drill 0.61)
  Top 0.254: 19.68,22.23 v21.59,20.32 | 19.68,22.23 19.05,22.86 E23.13 | 19.68,22.23 19.68,81.92 18.41,83.19 E25.14
  Bottom 0.254: v21.59,20.32 24.13,17.78 26.67,17.78 E20.4
MCLOCK\  (via drill 0.61)
  Top 0.254: v31.75,38.1 31.75,24.13 28.57,20.95 E20.3 | v152.4,15.24 152.4,18.41 154.94,20.95 154.94,46.99 158.75,46.99 159.38,46.35 159.38,45.09 158.12,43.81 E10.3
  Bottom 0.254: v31.75,38.1 30.48,39.37 20.32,39.37 19.05,40.64 E24.9 | 120.02,13.34 120.65,13.97 120.65,18.41 46.99,18.41 46.35,19.05 30.48,19.05 29.21,20.32 E20.3 | 120.02,13.34 118.75,12.06 108.58,12.06 104.78,8.26 J2.1 | v152.4,15.24 150.5,13.34 120.02,13.34
MPXA  (via drill 0.61)
  Top 0.254: 33.66,77.47 34.29,77.47 34.29,78.74 E22.14 | 33.66,77.47 26.67,77.47 26.04,78.11 26.04,85.09 16.51,85.09 15.88,84.45 15.88,70.48 17.14,69.22 E25.8 | v46.35,17.78 38.73,25.4 38.73,80.64 36.83,82.55 33.66,82.55 33.66,77.47
  Bottom 0.254: v46.35,17.78 106.68,17.78 108.58,15.88 J2.14
MPXB  (via drill 0.61)
  Top 0.254: v111.76,10.79 111.76,13.97 J2.13 | v109.22,10.16 110.49,8.89 110.49,6.35 108.58,4.45 99.69,4.45 99.69,7.62 93.98,13.34 38.1,13.34 38.1,78.74 36.2,80.64 E22.15
  Bottom 0.254: E25.9 16.51,71.12 15.24,69.85 8.89,69.85 8.26,70.48 8.26,80.01 13.97,80.01 16.51,77.47 19.05,77.47 24.13,82.55 29.21,82.55 30.48,81.28 34.29,81.28 E22.15 | v111.76,10.79 111.12,10.16 v109.22,10.16
N$1  (via drill 0.61)
  Top 0.254: v245.11,35.56 240.03,40.64 v240.03,54.61 | v170.18,55.24 167,52.07 167,47.62 165.74,46.35 E10.13
  Bottom 0.254: v245.11,35.56 250.19,35.56 E1.6 | v240.03,54.61 239.4,55.24 v170.18,55.24
N$2
  Bottom 0.254: E1.7 250.19,33.02 248.92,34.29 237.49,34.29 229.87,41.91 224.79,41.91 222.25,39.37 167.64,39.37 166.37,38.1 E10.10
N$3  (via drill 0.61)
  Top 0.254: v218.44,28.57 209.55,37.47 v209.55,40.64
  Bottom 0.254: v218.44,28.57 237.49,28.57 238.12,29.21 256.54,29.21 257.81,30.48 E1.9 | v209.55,40.64 208.28,41.91 160.02,41.91 158.75,40.64 E10.4
N$4  (via drill 0.61)
  Top 0.254: E20.11 36.2,18.41 37.47,19.68 37.47,38.73 36.2,40.01 E21.9 | v256.54,48.26 256.54,45.72 258.44,43.81 E1.14
  Bottom 0.254: v256.54,48.26 255.27,49.53 224.79,49.53 222.25,46.99 214,46.99 207.65,53.34 55.88,53.34 54.61,54.61 39.37,54.61 36.83,52.07 34.29,52.07 33.66,51.44 33.66,41.27 34.92,41.27 E21.9
N$5  (via drill 0.61)
  Top 0.254: v170.18,35.56 170.18,38.1 165.74,42.55 E10.12
  Bottom 0.254: v170.18,35.56 186.69,35.56 E6.6
N$6
  Bottom 0.254: E10.9 166.37,35.56 167,34.92 169.54,34.92 171.45,33.02 186.69,33.02 E6.7
N$7
  Bottom 0.254: E10.5 156.21,38.1 149.86,31.75 149.86,30.48 152.4,30.48 156.21,34.29 168.91,34.29 173.99,29.21 193.04,29.21 194.31,30.48 E6.9
N$8  (via drill 0.61)
  Top 0.254: v183.51,43.18 183.51,42.55 187.32,38.73 E6.5
  Bottom 0.254: v183.51,43.18 184.78,44.45 247.65,44.45 250.19,46.99 253.37,46.99 254.63,45.72 257.81,45.72 E1.15
N$9
  Bottom 0.254: E24.13 19.05,50.8 21.59,53.34 26.67,53.34 E21.1
N$10
  Bottom 0.254: E24.12 19.05,48.26 21.59,50.8 26.67,50.8 E21.2
N$11
  Bottom 0.254: E24.11 19.05,45.72 26.67,45.72 E21.4
N$12
  Top 0.254: E20.1 28.57,26.04 30.48,27.94 30.48,40.64 28.57,42.55 E21.5
  Bottom 0.254: E24.10 19.05,43.18 26.67,43.18 E21.5
N$13  (via drill 0.61)
  Top 0.254: v24.13,32.38 26.04,34.29 26.04,38.73 27.3,40.01 E21.6
  Bottom 0.254: v24.13,32.38 18.41,32.38 11.43,25.4 E23.1
N$14
  Bottom 0.254: E23.3 11.43,20.32 12.7,21.59 25.4,21.59 26.67,22.86 E20.2
N$15
  Top 0.254: E21.8 34.29,38.1 33.02,36.83 33.02,25.4 34.92,23.5 E20.13
  Bottom 0.254: E23.2 11.43,22.86 12.7,24.13 32.38,24.13 33.66,22.86 34.29,22.86 E20.13
N$16
  Bottom 0.254: E20.12 36.2,20.95 37.47,22.23 37.47,24.13 33.66,24.13 23.5,34.29 10.79,34.29 8.26,36.83 8.26,53.34 8.89,53.34 E24.1
N$17
  Bottom 0.254: E23.5 11.43,15.24 13.97,17.78 16.51,17.78 E23.11
N$18
  Top 0.254: E18.5 45.09,43.81 43.81,45.09 43.81,51.44 45.09,52.7 E18.1
N$19
  Top 0.254: R1.1 40.64,36.2 40.64,37.47 C18.1 40.64,38.73 39.37,40.01 39.37,48.9 40.64,50.16 C21.1
  Bottom 0.254: E18.7 44.45,38.1 41.27,38.1 C18.1
N$20
  Top 0.254: E18.15 53.98,51.44 60.33,57.78 C17.+
  Bottom 0.254: R2.2 58.42,60.33 59.69,59.05 60.33,59.05 C17.+
N$21
  Top 0.254: C18.2 40.64,43.81 40.64,45.09 C21.2
  Bottom 0.254: E18.6 44.45,40.64 41.91,43.18 41.27,43.18 C18.2
N$22
  Top 0.254: E18.14 54.61,48.26 60.33,42.55 C17.-
N$23  (via drill 0.61)
  Top 0.254: v214.63,38.1 219.71,43.18 E2.3
  Bottom 0.254: v214.63,38.1 196.85,38.1 E6.12
N$24
  Top 0.254: E18.4 46.35,45.09 52.7,38.73 E18.10
N$25
  Bottom 0.254: E6.11 196.85,35.56 198.12,34.29 224.79,34.29 227.33,36.83 229.87,36.83 230.5,37.47 230.5,40.01 229.24,40.01 E2.11
N$26
  Bottom 0.254: E6.10 196.85,33.02 197.49,32.38 219.07,32.38 219.71,31.75 225.43,31.75 226.69,33.02 227.33,33.02 E2.8
N$27  (via drill 0.61)
  Top 0.254: v102.23,54.61 95.89,48.26 95.89,41.27 60.33,41.27 58.42,43.18 54.61,43.18 E18.12 | v155.57,54.61 156.84,53.34 156.84,48.9 E10.1
  Bottom 0.254: v102.23,54.61 v155.57,54.61
N$28  (via drill 0.61)
  Top 0.254: v123.19,83.19 123.19,69.85 125.73,67.31 125.73,43.18 128.27,40.64 E16.13
  Bottom 0.254: v123.19,83.19 122.56,83.82 114.3,83.82 112.39,85.72 E15.7
N$29
  Top 0.254: E16.12 128.91,38.73 124.46,43.18 124.46,56.52 115.57,65.41 115.57,83.82 114.3,85.09 E15.6
N$30  (via drill 0.61)
  Top 0.254: v140.97,68.58 140.97,58.42 132.72,50.16 132.72,38.73 130.18,36.2 E16.11
  Bottom 0.254: v140.97,68.58 114.3,68.58 112.39,70.48 E15.4
N$31
  Top 0.254: E16.10 128.91,33.66 123.83,38.73 123.83,48.9 113.03,59.69 106.68,59.69 106.68,69.85 E15.2
N$32  (via drill 0.61)
  Top 0.254: v107.31,39.37 106.05,40.64 106.05,67.94 104.14,69.85 E15.1
  Bottom 0.254: v107.31,39.37 133.35,39.37 133.35,34.29 130.18,31.11 E16.9
N$33
  Top 0.254: E16.15 128.91,46.35 127.64,47.62 127.64,67.94 125.73,69.85 125.73,82.55 123.19,85.09 123.19,87.63 122.56,88.27 106.68,88.27 106.68,87.63 E15.9
N$34  (via drill 0.61)
  Top 0.254: v128.27,78.74 128.27,69.85 131.44,66.67 131.44,45.09 130.18,43.81 E16.14
  Bottom 0.254: v128.27,78.74 125.09,81.92 108.58,81.92 104.78,85.72 E15.10
N$35  (via drill 0.61)
  Top 0.254: v71.75,78.74 80.64,69.85 93.98,69.85 93.98,69.22 R24.2 93.98,67.94 93.98,66.67 R37.2
  Bottom 0.254: v71.75,78.74 54.61,78.74 E19.12
N$36
  Top 0.254: R25.2 88.9,67.94 88.9,66.67 R36.2
  Bottom 0.254: E19.10 54.61,73.66 55.24,73.03 81.28,73.03 85.09,69.22 85.09,66.67 88.9,66.67 R36.2
N$37
  Bottom 0.254: E25.11 19.05,76.2 20.32,77.47 33.02,77.47 34.29,76.2 E22.13
N$38  (via drill 0.61)
  Top 0.254: v224.79,46.99 225.43,46.35 225.43,22.86 R39.2
  Bottom 0.254: v224.79,46.99 239.4,46.99 240.66,48.26 D3.A
N$39
  Bottom 0.254: E25.1 11.43,83.82 16.51,78.74 E25.12
N$40
  Top 0.254: R35.2 83.82,66.67 83.82,67.94 R26.2
  Bottom 0.254: E19.8 54.61,68.58 55.88,67.31 81.92,67.31 83.19,68.58 R26.2
N$41
  Bottom 0.254: E22.1 29.21,83.82 30.48,82.55 50.8,82.55 52.07,81.28 E19.13
N$42
  Bottom 0.254: E22.2 29.21,81.28 30.48,80.01 46.99,80.01 50.8,76.2 52.07,76.2 E19.11
N$43
  Top 0.254: E22.3 28.57,79.38 34.29,85.09 51.44,85.09 51.44,73.03 52.7,71.75 E19.9
N$44
  Bottom 0.254: E22.4 29.21,76.2 30.48,74.93 40.64,74.93 44.45,78.74 E19.3
N$45
  Bottom 0.254: E22.5 29.21,73.66 30.48,72.39 43.18,72.39 44.45,73.66 E19.5
N$46
  Top 0.254: R34.2 78.74,66.67 78.74,67.94 R27.2
  Bottom 0.254: E19.4 46.99,76.2 50.8,72.39 74.3,72.39 78.11,68.58 R27.2
N$47
  Top 0.254: Q1.1 109.22,61.59 109.22,69.85 E15.3 109.22,72.39 109.22,85.09 E15.8
N$48
  Top 0.254: Q2.3 162.56,64.14 161.29,65.41 161.29,81.92 163.83,84.45 166.37,84.45 166.37,87.63 162.56,91.44 99.69,91.44 99.69,72.39 96.52,69.22 R29.2
N$49  (via drill 0.61)
  Top 0.254: v135.89,62.23 135.89,60.33 135.25,59.69 133.35,59.69 v133.35,63.5
  Bottom 0.254: v135.89,62.23 147.96,62.23 149.22,63.5 Q3.3 | v133.35,63.5 129.54,67.31 93.34,67.31 92.08,68.58 R30.2
N$50  (via drill 0.61)
  Top 0.254: v135.89,66.04 135.89,65.41 137.16,64.14 Q4.3
  Bottom 0.254: v135.89,66.04 133.99,67.94 99.06,67.94 97.16,69.85 88.27,69.85 87,68.58 R31.2
N$51  (via drill 0.61)
  Top 0.254: v82.55,64.77 81.28,66.04 81.28,67.94 R32.2
  Bottom 0.254: v82.55,64.77 122.56,64.77 123.83,63.5 Q5.3
N$52  (via drill 0.61)
  Top 0.254: v79.38,63.5 76.2,66.67 76.2,67.94 R33.2
  Bottom 0.254: v79.38,63.5 111.12,63.5 Q1.3
N$53
  Bottom 0.254: Q1.2 111.12,60.96 109.22,59.05 77.47,59.05 74.3,55.88 R38.1
N$54  (via drill 0.61)
  Top 0.254: E7.8 205.74,85.09 205.74,72.39 E7.3 205.1,70.48 v201.93,67.31 | Q5.1 121.92,61.59 121.92,69.85 E14.3 121.92,72.39 121.92,85.09 E14.8
  Bottom 0.254: v201.93,67.31 138.43,67.31 133.35,62.23 123.83,62.23 122.56,60.96 Q5.1
N$55
  Bottom 0.254: Q5.2 123.83,60.96 121.28,58.42 81.92,58.42 79.38,55.88 R34.1
N$56  (via drill 0.61)
  Top 0.254: v137.16,57.15 137.16,60.33 Q4.2
  Bottom 0.254: v137.16,57.15 85.72,57.15 84.45,55.88 R35.1
N$57  (via drill 0.61)
  Top 0.254: v132.72,59.05 v135.89,59.05
  Bottom 0.254: v135.89,59.05 147.32,59.05 149.22,60.96 Q3.2 | v132.72,59.05 131.44,57.78 83.82,57.78 82.55,56.52 82.55,54.61 87,54.61 88.27,55.88 R36.1
N$58  (via drill 0.61)
  Top 0.254: v157.48,56.52 161.93,60.96 Q2.2
  Bottom 0.254: v157.48,56.52 137.79,56.52 137.16,55.88 94.61,55.88 R37.1
N$59
  Top 0.254: R38.2 73.66,66.67 73.66,67.94 R28.2
  Bottom 0.254: E19.6 46.99,71.12 48.26,69.85 71.75,69.85 73.03,68.58 R28.2
N$60  (via drill 0.61)
  Top 0.254: 218.44,73.66 218.44,85.09 E5.8 | 218.44,73.66 218.44,72.39 E5.3 | Q4.1 134.62,61.59 134.62,69.85 E12.3 134.62,72.39 134.62,85.09 E12.8 | 218.44,73.66 207.01,73.66 207.01,67.94 v197.49,58.42
  Bottom 0.254: v197.49,58.42 136.53,58.42 135.89,57.78 134.62,59.05 134.62,60.33 Q4.1
N$61  (via drill 0.61)
  Top 0.254: E4.8 231.14,85.09 231.14,72.39 E4.3 230.5,70.48 v224.79,64.77 | Q3.1 147.32,61.59 147.32,69.85 E11.3 147.32,72.39 147.32,85.09 E11.8
  Bottom 0.254: v224.79,64.77 172.72,64.77 170.18,62.23 149.22,62.23 147.96,60.96 Q3.1
N$62
  Top 0.254: E3.3 243.84,72.39 243.84,85.09 E3.8 | Q2.1 160.02,61.59 160.02,69.85 E9.3 160.02,72.39 160.02,85.09 E9.8
  Bottom 0.254: E3.8 243.21,87 241.3,88.9 191.13,88.9 185.42,83.19 163.19,83.19 160.66,85.72 E9.8
N$63
  Top 0.254: D6.A 210.82,47.62 213.36,45.09 213.36,34.92 223.52,24.77 223.52,23.5 R40.2
N$64  (via drill 0.61)
  Top 0.254: v233.68,23.5 240.66,30.48 D2.A
  Bottom 0.254: v233.68,23.5 233.04,24.13 230.5,24.13 229.24,22.86 R41.2
N$65
  Top 0.254: D5.A 211.46,30.48 217.81,24.13 220.98,24.13 220.98,23.5 R42.2
N$66
  Top 0.254: D7.A 180.34,29.84 180.97,29.21 180.97,25.4 182.88,23.5 R43.2
N$67
  Top 0.254: D1.A 240.66,12.7 231.14,22.23 R44.2
N$68
  Top 0.254: D4.A 210.82,13.34 218.44,20.95 218.44,22.23 R45.2
N$69
  Top 0.254: D8.A 180.34,47.62 181.61,46.35 181.61,27.3 185.42,23.5 R46.2
N$70  (via drill 0.61)
  Top 0.254: v172.72,77.47 173.35,76.83 173.35,53.34 177.8,48.9 D8.K
  Bottom 0.254: v172.72,77.47 50.8,77.47 46.99,81.28 E19.2
N$71  (via drill 0.61)
  Top 0.254: v95.89,40.01 96.52,39.37 v96.52,12.06
  Bottom 0.254: v95.89,40.01 103.5,47.62 E17.1 | v96.52,12.06 102.87,5.71 175.26,5.71 180.97,11.43 206.38,11.43 207.65,12.7 D4.K
N$72  (via drill 0.61)
  Top 0.254: v166.37,21.59 169.54,18.41 v169.54,15.24
  Bottom 0.254: v166.37,21.59 91.44,21.59 91.44,33.02 103.5,45.09 E17.2 | v169.54,15.24 233.68,15.24 236.22,12.7 238.12,12.7 D1.K
N$73  (via drill 0.61)
  Top 0.254: v107.31,40.64 108.58,39.37 v108.58,27.94 | v175.26,25.4 177.8,27.94 177.8,29.84 D7.K
  Bottom 0.254: v107.31,40.64 106.68,40.64 104.78,42.55 E17.3 | v108.58,27.94 111.12,25.4 v175.26,25.4
N$74  (via drill 0.61)
  Top 0.254: v102.23,52.07 102.23,42.55 103.5,41.27 E17.4 | v198.12,52.07 208.28,41.91 208.28,31.11 D5.K
  Bottom 0.254: v102.23,52.07 v198.12,52.07
N$75  (via drill 0.61)
  Top 0.254: v134.62,17.78 132.08,20.32 v132.08,35.56
  Bottom 0.254: v134.62,17.78 168.91,17.78 175.9,24.77 194.94,24.77 195.58,25.4 207.65,25.4 212.09,29.84 218.44,29.84 219.07,29.21 236.85,29.21 238.12,30.48 D2.K | v132.08,35.56 130.81,36.83 106.68,36.83 105.41,38.1 E17.5
N$76  (via drill 0.61)
  Top 0.254: v117.47,34.29 117.47,45.09 116.84,45.72 v116.84,50.8
  Bottom 0.254: v117.47,34.29 106.68,34.29 105.41,35.56 E17.6 | v116.84,50.8 117.47,51.44 197.49,51.44 200.66,48.26 207.65,48.26 D6.K
N$77  (via drill 0.61)
  Top 0.254: v118.11,31.75 118.11,6.35 120.65,3.81 177.16,3.81 177.16,7.62 180.97,11.43 229.87,11.43 229.87,26.04 238.76,34.92 238.76,47.62 D3.K
  Bottom 0.254: v118.11,31.75 106.68,31.75 105.41,33.02 E17.7
NUM
  Bottom 0.254: E20.10 36.83,15.24 37.47,15.88 100.33,15.88 102.87,13.34 114.94,13.34 116.2,14.61 J2.11
RUN
  Top 0.254: E2.2 220.34,46.35 219.07,47.62 219.07,50.8 220.98,52.7 R9.2 | RUN.1 376.56,6.35 376.56,16.51 RUN.2
  Bottom 0.254: R9.2 221.62,53.34 222.88,54.61 238.76,54.61 240.03,53.34 358.77,53.34 377.82,34.29 377.82,19.05 376.56,19.05 RUN.2
SHLT\  (via drill 0.61)
  Top 0.254: SHLT\.1 353.69,6.35 353.69,16.51 SHLT\.2 | 196.85,20.95 189.23,20.95 176.53,8.26 176.53,4.45 132.72,4.45 130.81,6.35 130.81,9.53 140.34,9.53 141.6,8.26 J1.5 | 196.85,20.95 196.85,23.5 193.04,27.3 193.04,48.26 198.12,53.34 217.81,53.34 R19.2 | 196.85,20.95 v198.12,19.68
  Bottom 0.254: E2.1 220.34,48.9 220.34,52.07 219.07,53.34 R19.2 | v198.12,19.68 230.5,19.68 234.95,15.24 351.15,15.24 352.43,16.51 SHLT\.2
STHIS\  (via drill 0.61)
  Top 0.254: v151.13,31.75 151.13,5.71 141.6,5.71 140.34,6.99 J1.4
  Bottom 0.254: v151.13,31.75 156.21,36.83 218.44,36.83 219.71,35.56 E2.6
VCC  (via drill 0.61)
  Top 0.635: R29.1 95.89,78.74 94.61,78.74 R24.1 93.34,78.74 92.08,78.74 R30.1 90.81,78.74 89.53,78.74 R25.1 88.27,78.74 87,78.74 R31.1 85.72,78.74 84.45,78.74 R26.1 83.19,78.74 81.92,78.74 R32.1 80.64,78.74 79.38,78.74 R27.1 78.11,78.74 76.83,78.74 R33.1 75.56,78.74 74.3,78.74 R28.1 73.66,79.38 73.66,83.82 54.61,83.82 E19.14 53.98,83.19 55.24,81.92 55.24,67.31 48.9,60.96 R2.1 | C20.+ 85.09,50.16 92.71,50.16 C19.+ | E21.14 34.92,53.98 34.29,54.61 34.29,62.87 C13.1 | R2.1 48.26,61.59 52.07,65.41 C10.1 | E18.3 46.99,48.26 52.07,53.34 E18.16 52.7,53.98 52.7,55.88 48.26,60.33 R2.1 | E24.2 9.53,50.16 9.53,48.9 E24.3 9.53,47.62 9.53,46.35 E24.4 9.53,45.09 9.53,43.81 E24.5 11.43,43.18 16.51,38.1 E24.8 17.14,37.47 16.51,36.83 16.51,36.2 C15.1 16.51,34.92 16.51,26.67 17.14,26.04 E23.14 17.14,24.77 15.88,23.5 15.88,18.41 | E24.14 17.14,53.98 17.14,64.77 16.51,65.41 C16.1 16.51,66.67 16.51,67.31 10.79,73.03 E25.5 | C12.1 34.29,34.92 34.92,34.29 34.92,26.04 E20.14 | 15.88,13.34 15.88,8.89 16.51,8.26 C14.1 | 15.88,13.34 17.14,14.61 E23.10 | 15.88,18.41 17.14,19.68 E23.12 | 15.88,18.41 15.88,13.34 | E8.16 181.61,81.28 176.53,76.2 E8.3 174.62,75.56 174.62,74.3 E8.4 174.62,73.03 174.62,71.75 E8.5 175.9,70.48 178.44,67.94 178.44,64.77 181.61,61.59 C4.1 181.61,60.33 v181.61,50.16 | 255.27,48.9 255.27,29.84 257.18,27.94 C1.1 | 255.27,48.9 255.91,49.53 258.44,49.53 258.44,48.9 E1.16 | R9.1 221.62,63.5 222.88,63.5 R22.1 224.16,63.5 225.43,63.5 R23.1 | 233.04,55.88 233.04,60.96 231.14,62.87 R21.1 | 233.04,55.88 v233.04,48.26 233.04,30.48 227.97,30.48 C2.1 | 255.27,48.9 253.37,48.9 246.38,55.88 233.04,55.88
  Top 0.635: R4.1 116.84,31.11 116.2,31.75 116.2,43.81 112.39,47.62 E17.16 110.49,48.26 v107.95,50.8 | E13.5 139.06,38.73 139.06,40.01 E13.4 139.06,41.27 139.06,42.55 E13.3 | J2.16 104.78,14.61 106.05,13.34 107.95,13.34 107.95,24.77 110.49,27.3 C8.1 | J1.16 132.08,16.51 128.27,20.32 128.27,27.3 C7.1 128.27,28.57 123.83,33.02 123.83,36.2 122.56,37.47 E16.5 121.28,38.73 121.28,40.01 E16.4 121.28,41.27 121.28,42.55 E16.3 | R45.1 219.07,12.7 220.34,12.7 R42.1 221.62,12.7 222.88,12.7 R40.1 224.16,12.7 225.43,12.7 R39.1 226.69,12.7 227.97,12.7 R41.1 | R18.1 247.01,12.7 248.28,12.7 R17.1 249.56,12.7 250.82,12.7 R16.1 252.09,12.7 253.37,12.7 R15.1 254.63,12.7 255.91,12.7 R14.1 257.18,12.7 258.44,12.7 R13.1 259.71,12.7 260.99,12.7 R11.1 262.25,12.7 263.52,12.7 R12.1 | R43.1 183.51,12.7 184.78,12.7 R46.1 186.06,12.7 187.32,12.7 R3.1 188.59,12.7 189.87,12.7 R5.1 191.13,12.7 192.41,12.7 R7.1 193.68,12.7 194.94,12.7 R6.1 196.22,12.7 197.49,12.7 R8.1 198.12,13.34 200.66,15.88 200.66,43.18 196.22,47.62 E6.16 | C5.1 163.83,29.84 v163.83,26.67 163.83,10.79 161.93,8.89 160.02,8.89 160.02,12.06 R10.1
  Bottom 0.635: E22.16 36.83,83.82 38.1,85.09 50.8,85.09 52.07,83.82 E19.14 | C13.1 34.92,63.5 37.47,60.96 47.62,60.96 R2.1 | C20.+ 82.55,51.44 56.52,51.44 54.61,53.34 E18.16 | E24.2 11.43,50.8 13.97,50.8 16.51,53.34 E24.14 19.05,53.34 20.32,54.61 33.02,54.61 34.29,53.34 E21.14 | E20.14 36.83,25.4 40.01,25.4 R1.2 41.27,25.4 43.81,25.4 51.44,33.02 C9.1 | E23.12 16.51,20.32 13.97,20.32 11.43,17.78 E23.4 9.53,18.41 8.26,18.41 8.26,29.21 VCC.1 | C11.1 33.66,7.62 32.38,6.35 18.41,6.35 17.14,7.62 C14.1 | C12.1 33.66,35.56 32.38,34.29 24.77,34.29 23.5,35.56 17.14,35.56 C15.1 | R9.1 220.34,63.5 219.07,63.5 R19.1 217.81,63.5 216.53,62.23 183.51,62.23 182.25,60.96 C4.1 | R23.1 226.69,63.5 227.97,63.5 R20.1 229.24,63.5 230.5,63.5 R21.1 | v233.04,48.26 229.87,48.26 E2.14 | E16.16 130.81,48.26 134.62,48.26 139.06,43.81 E13.3 138.43,43.18 137.16,41.91 124.46,41.91 123.19,43.18 E16.3 120.65,43.18 118.11,43.18 113.03,48.26 E17.16 | 144.15,26.67 145.41,27.94 C6.1 | 144.15,26.67 130.18,26.67 | 130.18,26.67 128.91,27.94 C7.1 | 144.15,26.67 v163.83,26.67 192.41,26.67 193.68,27.94 C3.1 | 130.18,26.67 112.39,26.67 111.12,27.94 C8.1 | 162.56,49.53 149.86,49.53 148.59,48.26 E13.16 | 162.56,49.53 163.83,48.26 E10.14 | 181.61,49.53 162.56,49.53 | 181.61,49.53 193.04,49.53 194.31,48.26 E6.16 | R41.1 229.24,12.7 230.5,12.7 R44.1 231.78,12.7 233.04,11.43 244.47,11.43 245.75,12.7 R18.1 | R43.1 182.25,12.7 160.66,12.7 R10.1 | R45.1 217.81,12.7 216.53,13.97 200.03,13.97 198.75,12.7 R8.1 | 181.61,49.53 v181.61,50.16 | v107.95,50.8 95.25,50.8 C19.+
  pour Bottom (isolate 0.254): 0,0 0,93.98 393.7,93.98 393.7,0

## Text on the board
Top: Revision A | VRS/CEM | PDP-8/A Console, Board 1
Bottom: Warning - VCC Fill | Warning - VCC Fill | Warning - VCC Fill | Revision A | VRS/CEM | PDP-8/A Console, Board 1
tPlace: Revision A
tValues: VRS/CEM | PDP-8/A Console, Board 1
